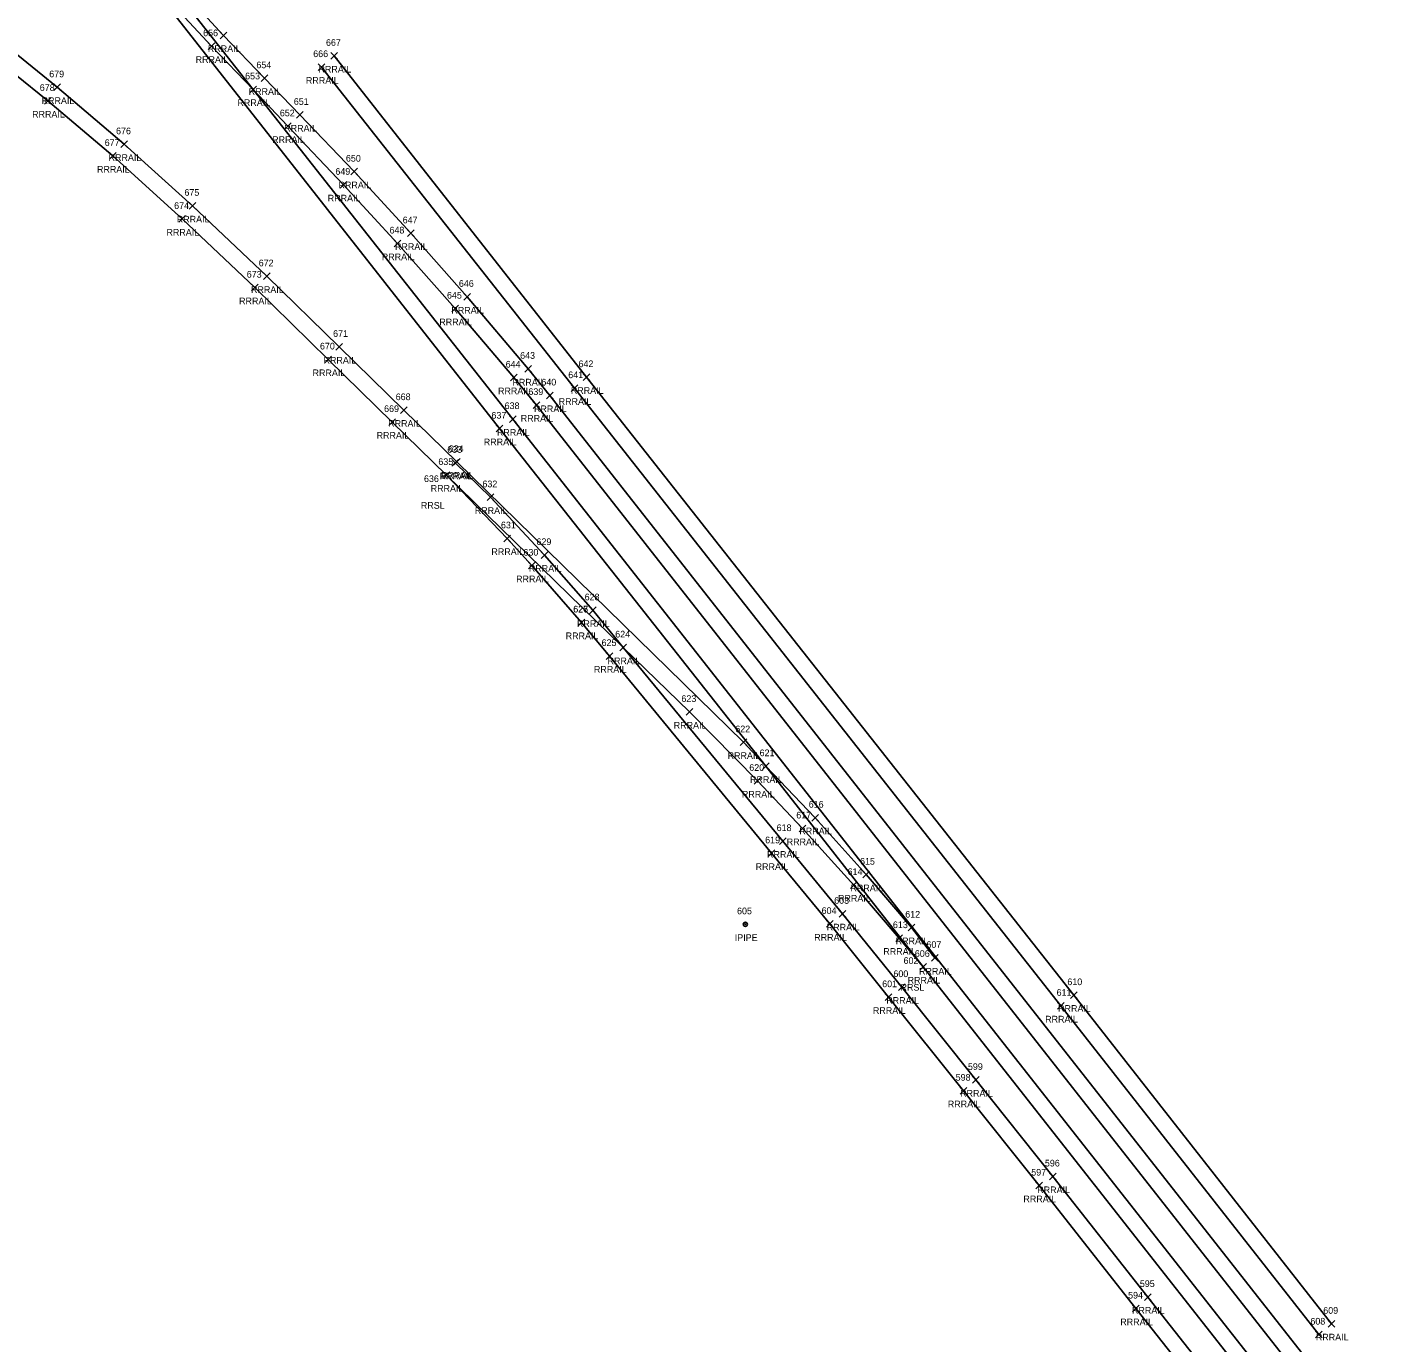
# Model space of a CAD drawing. Extents: x 1615599 to 1619911, y 273782 to 280437.
# Drawn here: x 1616569.8 to 1616981.6, y 279351.3 to 279745.5 of the extents above; entities that cross this region are included whole.
import ezdxf

# ---------------------------------------------------------------- set-up
doc = ezdxf.new("R2010")
doc.units = 0
for name, color, linetype in [('M_A', 7, 'Continuous'), ('M_I', 7, 'Continuous'), ('MPIP', 7, 'Continuous'), ('R_A', 7, 'Continuous'), ('R_I', 7, 'Continuous'), ('R_TIC', 7, 'Continuous'), ('RR', 7, 'Continuous')]:
    doc.layers.add(name, color=color, linetype=linetype)

msp = doc.modelspace()

# ---------------------------------------------------------------- linework, layer by layer
at = {"layer": 'MPIP'}
for radius in [0.625, 0.0833]:
    msp.add_circle((1616785.13, 279476.65), radius, dxfattribs=at)
at = {"layer": 'R_TIC'}
for points in [[(1616627.65, 279742.11), (1616629.65, 279744.11)], [(1616629.65, 279742.11), (1616627.65, 279744.11)], [(1616623.98, 279738.87), (1616625.98, 279740.87)], [(1616625.98, 279738.87), (1616623.98, 279740.87)], [(1616660.82, 279735.98), (1616662.82, 279737.98)], [(1616662.82, 279735.98), (1616660.82, 279737.98)], [(1616657.05, 279732.61), (1616659.05, 279734.61)], [(1616659.05, 279732.61), (1616657.05, 279734.61)], [(1616639.89, 279729.27), (1616641.89, 279731.27)], [(1616641.89, 279729.27), (1616639.89, 279731.27)], [(1616574.93, 279722.48), (1616576.93, 279724.48)], [(1616576.93, 279722.48), (1616574.93, 279724.48)], [(1616577.78, 279726.56), (1616579.78, 279728.56)], [(1616579.78, 279726.56), (1616577.78, 279728.56)], [(1616636.52, 279725.94), (1616638.52, 279727.94)], [(1616638.52, 279725.94), (1616636.52, 279727.94)], [(1616636.52, 279725.94), (1616638.52, 279727.94)], [(1616638.52, 279725.94), (1616636.52, 279727.94)], [(1616646.93, 279714.86), (1616648.93, 279716.86)], [(1616648.93, 279714.86), (1616646.93, 279716.86)], [(1616650.55, 279718.29), (1616652.55, 279720.29)], [(1616652.55, 279718.29), (1616650.55, 279720.29)], [(1616594.4, 279705.97), (1616596.4, 279707.97)], [(1616596.4, 279705.97), (1616594.4, 279707.97)], [(1616597.87, 279709.48), (1616599.87, 279711.48)], [(1616599.87, 279709.48), (1616597.87, 279711.48)], [(1616666.83, 279701.27), (1616668.83, 279703.27)], [(1616668.83, 279701.27), (1616666.83, 279703.27)], [(1616663.6, 279697.33), (1616665.6, 279699.33)], [(1616665.6, 279697.33), (1616663.6, 279699.33)], [(1616618.31, 279691.03), (1616620.31, 279693.03)], [(1616620.31, 279691.03), (1616618.31, 279693.03)], [(1616615.23, 279687.08), (1616617.23, 279689.08)], [(1616617.23, 279687.08), (1616615.23, 279689.08)], [(1616683.77, 279682.78), (1616685.77, 279684.78)], [(1616685.77, 279682.78), (1616683.77, 279684.78)], [(1616679.81, 279679.73), (1616681.81, 279681.73)], [(1616681.81, 279679.73), (1616679.81, 279681.73)], [(1616640.59, 279669.9), (1616642.59, 279671.9)], [(1616642.59, 279669.9), (1616640.59, 279671.9)], [(1616637.01, 279666.5), (1616639.01, 279668.5)], [(1616639.01, 279666.5), (1616637.01, 279668.5)], [(1616700.68, 279663.74), (1616702.68, 279665.74)], [(1616702.68, 279663.74), (1616700.68, 279665.74)], [(1616697.06, 279660.21), (1616699.06, 279662.21)], [(1616699.06, 279660.21), (1616697.06, 279662.21)], [(1616662.34, 279648.74), (1616664.34, 279650.74)], [(1616664.34, 279648.74), (1616662.34, 279650.74)], [(1616659.04, 279644.96), (1616661.04, 279646.96)], [(1616661.04, 279644.96), (1616659.04, 279646.96)], [(1616719, 279642.16), (1616721, 279644.16)], [(1616721, 279642.16), (1616719, 279644.16)], [(1616714.66, 279639.54), (1616716.66, 279641.54)], [(1616716.66, 279639.54), (1616714.66, 279641.54)], [(1616732.86, 279636.36), (1616734.86, 279638.36)], [(1616734.86, 279636.36), (1616732.86, 279638.36)], [(1616736.5, 279639.66), (1616738.5, 279641.66)], [(1616738.5, 279639.66), (1616736.5, 279641.66)], [(1616725.46, 279634.17), (1616727.46, 279636.17)], [(1616727.46, 279634.17), (1616725.46, 279636.17)], [(1616681.72, 279629.77), (1616683.72, 279631.77)], [(1616683.72, 279629.77), (1616681.72, 279631.77)], [(1616721.48, 279631.31), (1616723.48, 279633.31)], [(1616723.48, 279631.31), (1616721.48, 279633.31)], [(1616678.25, 279626.2), (1616680.25, 279628.2)], [(1616680.25, 279626.2), (1616678.25, 279628.2)], [(1616710.4, 279624.23), (1616712.4, 279626.23)], [(1616712.4, 279624.23), (1616710.4, 279626.23)], [(1616714.35, 279627.09), (1616716.35, 279629.09)], [(1616716.35, 279627.09), (1616714.35, 279629.09)], [(1616697.15, 279613.99), (1616699.15, 279615.99)], [(1616699.15, 279613.99), (1616697.15, 279615.99)], [(1616697.57, 279614.23), (1616699.57, 279616.23)], [(1616699.57, 279614.23), (1616697.57, 279616.23)], [(1616694.47, 279610.31), (1616696.47, 279612.31)], [(1616696.47, 279610.31), (1616694.47, 279612.31)], [(1616694.47, 279610.31), (1616696.47, 279612.31)], [(1616696.47, 279610.31), (1616694.47, 279612.31)], [(1616707.69, 279603.66), (1616709.69, 279605.66)], [(1616709.69, 279603.66), (1616707.69, 279605.66)], [(1616712.69, 279591.34), (1616714.69, 279593.34)], [(1616714.69, 279591.34), (1616712.69, 279593.34)], [(1616720.09, 279583.16), (1616722.09, 279585.16)], [(1616722.09, 279583.16), (1616720.09, 279585.16)], [(1616723.91, 279586.33), (1616725.91, 279588.33)], [(1616725.91, 279586.33), (1616723.91, 279588.33)], [(1616734.96, 279566.13), (1616736.96, 279568.13)], [(1616736.96, 279566.13), (1616734.96, 279568.13)], [(1616734.96, 279566.11), (1616736.96, 279568.11)], [(1616736.96, 279566.11), (1616734.96, 279568.11)], [(1616738.35, 279569.76), (1616740.35, 279571.76)], [(1616740.35, 279569.76), (1616738.35, 279571.76)], [(1616747.52, 279558.62), (1616749.52, 279560.62)], [(1616749.52, 279558.62), (1616747.52, 279560.62)], [(1616747.52, 279558.62), (1616749.52, 279560.62)], [(1616749.52, 279558.62), (1616747.52, 279560.62)], [(1616743.42, 279556.06), (1616745.42, 279558.06)], [(1616745.42, 279556.06), (1616743.42, 279558.06)], [(1616767.37, 279539.29), (1616769.37, 279541.29)], [(1616769.37, 279539.29), (1616767.37, 279541.29)], [(1616783.53, 279530.21), (1616785.53, 279532.21)], [(1616785.53, 279530.21), (1616783.53, 279532.21)], [(1616790.25, 279523.04), (1616792.25, 279525.04)], [(1616792.25, 279523.04), (1616790.25, 279525.04)], [(1616790.25, 279523.04), (1616792.25, 279525.04)], [(1616792.25, 279523.04), (1616790.25, 279525.04)], [(1616787.81, 279518.63), (1616789.81, 279520.63)], [(1616789.81, 279518.63), (1616787.81, 279520.63)], [(1616801.25, 279504.36), (1616803.25, 279506.36)], [(1616803.25, 279504.36), (1616801.25, 279506.36)], [(1616805.04, 279507.6), (1616807.04, 279509.6)], [(1616807.04, 279507.6), (1616805.04, 279509.6)], [(1616795.36, 279500.58), (1616797.36, 279502.58)], [(1616797.36, 279500.58), (1616795.36, 279502.58)], [(1616791.93, 279496.92), (1616793.93, 279498.92)], [(1616793.93, 279496.92), (1616791.93, 279498.92)], [(1616820.37, 279490.52), (1616822.37, 279492.52)], [(1616822.37, 279490.52), (1616820.37, 279492.52)], [(1616816.64, 279487.42), (1616818.64, 279489.42)], [(1616818.64, 279487.42), (1616816.64, 279489.42)], [(1616809.5, 279475.75), (1616811.5, 279477.75)], [(1616811.5, 279475.75), (1616809.5, 279477.75)], [(1616809.5, 279475.75), (1616811.5, 279477.75)], [(1616811.5, 279475.75), (1616809.5, 279477.75)], [(1616813.26, 279478.79), (1616815.26, 279480.79)], [(1616815.26, 279478.79), (1616813.26, 279480.79)], [(1616813.26, 279478.79), (1616815.26, 279480.79)], [(1616815.26, 279478.79), (1616813.26, 279480.79)], [(1616830.23, 279471.5), (1616832.23, 279473.5)], [(1616832.23, 279471.5), (1616830.23, 279473.5)], [(1616833.94, 279474.65), (1616835.94, 279476.65)], [(1616835.94, 279474.65), (1616833.94, 279476.65)], [(1616840.94, 279465.55), (1616842.94, 279467.55)], [(1616842.94, 279465.55), (1616840.94, 279467.55)], [(1616837.51, 279462.88), (1616839.51, 279464.88)], [(1616839.51, 279462.88), (1616837.51, 279464.88)], [(1616837.51, 279462.88), (1616839.51, 279464.88)], [(1616839.51, 279462.88), (1616837.51, 279464.88)], [(1616831.11, 279456.81), (1616833.11, 279458.81)], [(1616833.11, 279456.81), (1616831.11, 279458.81)], [(1616827.1, 279453.79), (1616829.1, 279455.79)], [(1616829.1, 279453.79), (1616827.1, 279455.79)], [(1616878.76, 279451.2), (1616880.76, 279453.2)], [(1616880.76, 279451.2), (1616878.76, 279453.2)], [(1616882.64, 279454.4), (1616884.64, 279456.4)], [(1616884.64, 279454.4), (1616882.64, 279456.4)], [(1616853.26, 279428.97), (1616855.26, 279430.97)], [(1616855.26, 279428.97), (1616853.26, 279430.97)], [(1616849.57, 279425.76), (1616851.57, 279427.76)], [(1616851.57, 279425.76), (1616849.57, 279427.76)], [(1616872.24, 279397.31), (1616874.24, 279399.31)], [(1616874.24, 279397.31), (1616872.24, 279399.31)], [(1616876.39, 279400.04), (1616878.39, 279402.04)], [(1616878.39, 279400.04), (1616876.39, 279402.04)], [(1616901.29, 279360.44), (1616903.29, 279362.44)], [(1616903.29, 279360.44), (1616901.29, 279362.44)], [(1616904.81, 279363.9), (1616906.81, 279365.9)], [(1616906.81, 279363.9), (1616904.81, 279365.9)], [(1616956.09, 279352.64), (1616958.09, 279354.64)], [(1616958.09, 279352.64), (1616956.09, 279354.64)], [(1616959.95, 279355.88), (1616961.95, 279357.88)], [(1616961.95, 279355.88), (1616959.95, 279357.88)]]:
    msp.add_lwpolyline(points, dxfattribs=at)
at = {"layer": 'RR'}
for points in [[(1618859.75, 276891.53), (1618799.24, 276968.15), (1618284.94, 277623.12), (1618268.81, 277643.64), (1617626.81, 278460.24), (1617616.13, 278473.64), (1617546.95, 278561.72), (1617499.49, 278621.79), (1617406.55, 278740.52), (1617357.63, 278802.9), (1617271.97, 278912.55), (1616838.51, 279463.88), (1616791.25, 279524.04), (1616711.4, 279625.23), (1616195.43, 280281.84), (1616147.06, 280342.91)], [(1618863.67, 276894.43), (1618803.13, 276971.25), (1618287.89, 277627.49), (1618272.16, 277647.46), (1617630.42, 278463.6), (1617620.37, 278476.22), (1617582.75, 278523.92), (1617266.97, 278926.89), (1616715.35, 279628.09), (1616637.52, 279726.94), (1616590.36, 279786.85), (1616151.06, 280346.19)], [(1617630.42, 278463.6), (1617620.82, 278476.43), (1617606.54, 278496.62), (1617593.5, 278516.12), (1617586.3, 278527.38), (1617567.87, 278556.66), (1617553.59, 278578.19), (1617540.33, 278596.98), (1617518.68, 278626.03), (1617484.75, 278670.09), (1617274.79, 278937.46), (1616726.46, 279635.17), (1616720, 279643.16), (1616701.68, 279664.74), (1616684.77, 279683.78), (1616667.83, 279702.27), (1616651.55, 279719.29), (1616640.89, 279730.27), (1616628.65, 279743.11), (1616617.88, 279754.77), (1616607.15, 279767.18), (1616599.77, 279774.94), (1616590.36, 279786.85)], [(1617627.18, 278460.59), (1617616.67, 278473.78), (1617602.72, 278493.41), (1617589.08, 278513.87), (1617582.75, 278523.92), (1617563.26, 278554.55), (1617549.48, 278575.26), (1617536.29, 278594.04), (1617514.68, 278623.03), (1617480.83, 278667.07), (1617271.03, 278934.24), (1616722.48, 279632.31), (1616715.66, 279640.54), (1616698.06, 279661.21), (1616680.81, 279680.73), (1616664.6, 279698.33), (1616647.93, 279715.86), (1616637.52, 279726.94), (1616624.98, 279739.87), (1616614.3, 279751.39), (1616603.44, 279763.78), (1616596.48, 279772.09), (1616586.32, 279784.93)], [(1616841.94, 279466.55), (1616834.94, 279475.65), (1616821.37, 279491.52), (1616806.04, 279508.6), (1616791.25, 279524.04), (1616784.53, 279531.21), (1616698.57, 279615.23), (1616682.72, 279630.77), (1616663.34, 279649.74), (1616641.59, 279670.9), (1616619.31, 279692.03), (1616598.87, 279710.48), (1616578.78, 279727.56), (1616559.36, 279743.25)], [(1616838.51, 279463.88), (1616831.23, 279472.5), (1616817.64, 279488.42), (1616802.25, 279505.36), (1616788.81, 279519.63), (1616768.37, 279540.29), (1616748.52, 279559.62), (1616695.47, 279611.31), (1616679.25, 279627.2), (1616660.04, 279645.96), (1616638.01, 279667.5), (1616616.23, 279688.08), (1616595.4, 279706.97), (1616575.93, 279723.48), (1616556.08, 279739.45)], [(1616960.95, 279356.88), (1616883.64, 279455.4), (1616737.5, 279640.66), (1616661.82, 279736.98)], [(1616957.09, 279353.64), (1616879.76, 279452.2), (1616733.86, 279637.36), (1616658.05, 279733.61)], [(1616814.26, 279479.79), (1616796.36, 279501.58), (1616748.52, 279559.62), (1616739.35, 279570.76), (1616724.91, 279587.33), (1616708.69, 279604.66), (1616698.15, 279614.99)], [(1616810.5, 279476.75), (1616792.93, 279497.92), (1616744.42, 279557.06), (1616735.96, 279567.13), (1616735.96, 279567.11), (1616721.09, 279584.16), (1616713.69, 279592.34), (1616695.47, 279611.31)], [(1617410, 278743.26), (1617396.66, 278759.99), (1617376.07, 278783.25), (1617357.63, 278802.9), (1617338.99, 278821.92), (1617323.11, 278838.2), (1617305.76, 278857.56), (1617286.13, 278880.85), (1617265.43, 278906.99), (1617008.7, 279234.06), (1616973.07, 279279.43), (1616937.09, 279325.15), (1616905.81, 279364.9), (1616877.39, 279401.04), (1616854.26, 279429.97), (1616832.11, 279457.81), (1616814.26, 279479.79)], [(1617406.55, 278740.52), (1617392.93, 278756.85), (1617371.79, 278780.66), (1617353.75, 278799.89), (1617335.51, 278818.43), (1617319.77, 278834.69), (1617301.78, 278854.53), (1617282.18, 278877.78), (1617261.42, 278904), (1617004.64, 279231.09), (1616969.14, 279276.29), (1616932.72, 279322.9), (1616902.29, 279361.44), (1616873.24, 279398.31), (1616850.57, 279426.76), (1616828.1, 279454.79), (1616810.5, 279476.75)]]:
    msp.add_lwpolyline(points, dxfattribs=at)

# ---------------------------------------------------------------- texts
at = {"layer": 'M_A'}
msp.add_text('IPIPE', height=2, dxfattribs=at).set_placement((1616781.96, 279471.65))
at = {"layer": 'M_I'}
msp.add_text('605', height=2, dxfattribs=at).set_placement((1616782.64, 279479.65))
at = {"layer": 'R_A'}
for s, p in [('RRRAIL', (1616620.27, 279734.87)), ('RRRAIL', (1616623.94, 279738.11)), ('RRRAIL', (1616657.11, 279731.98)), ('RRRAIL', (1616653.34, 279728.61)), ('RRRAIL', (1616574.07, 279722.56)), ('RRRAIL', (1616636.18, 279725.27)), ('RRRAIL', (1616571.22, 279718.48)), ('RRRAIL', (1616632.81, 279721.94)), ('RRRAIL', (1616632.81, 279721.94)), ('RRRAIL', (1616646.84, 279714.29)), ('RRRAIL', (1616643.22, 279710.86)), ('RRRAIL', (1616590.69, 279701.97)), ('RRRAIL', (1616594.16, 279705.48)), ('RRRAIL', (1616663.12, 279697.27)), ('RRRAIL', (1616659.89, 279693.33)), ('RRRAIL', (1616614.61, 279687.03)), ('RRRAIL', (1616611.52, 279683.08)), ('RRRAIL', (1616680.06, 279678.78)), ('RRRAIL', (1616676.1, 279675.73)), ('RRRAIL', (1616636.88, 279665.9)), ('RRRAIL', (1616633.3, 279662.5)), ('RRRAIL', (1616696.97, 279659.74)), ('RRRAIL', (1616693.35, 279656.21)), ('RRRAIL', (1616658.63, 279644.74)), ('RRRAIL', (1616655.34, 279640.96)), ('RRRAIL', (1616715.29, 279638.16)), ('RRRAIL', (1616710.95, 279635.54)), ('RRRAIL', (1616729.15, 279632.36)), ('RRRAIL', (1616732.79, 279635.66)), ('RRRAIL', (1616721.75, 279630.17)), ('RRRAIL', (1616678.02, 279625.77)), ('RRRAIL', (1616717.77, 279627.31)), ('RRRAIL', (1616674.55, 279622.2)), ('RRRAIL', (1616706.69, 279620.23)), ('RRRAIL', (1616710.64, 279623.09)), ('RRRAIL', (1616693.44, 279609.99)), ('RRRAIL', (1616693.86, 279610.23)), ('RRRAIL', (1616690.76, 279606.31)), ('RRRAIL', (1616690.76, 279606.31)), ('RRSL', (1616687.82, 279601.21)), ('RRRAIL', (1616703.99, 279599.66)), ('RRRAIL', (1616708.98, 279587.34)), ('RRRAIL', (1616716.38, 279579.16)), ('RRRAIL', (1616720.2, 279582.33)), ('RRRAIL', (1616731.25, 279562.13)), ('RRRAIL', (1616731.25, 279562.11)), ('RRRAIL', (1616734.64, 279565.76)), ('RRRAIL', (1616743.81, 279554.62)), ('RRRAIL', (1616743.81, 279554.62)), ('RRRAIL', (1616739.72, 279552.06)), ('RRRAIL', (1616763.66, 279535.29)), ('RRRAIL', (1616779.82, 279526.21)), ('RRRAIL', (1616786.54, 279519.04)), ('RRRAIL', (1616786.54, 279519.04)), ('RRRAIL', (1616784.1, 279514.63)), ('RRRAIL', (1616797.54, 279500.36)), ('RRRAIL', (1616801.33, 279503.6)), ('RRRAIL', (1616791.65, 279496.58)), ('RRRAIL', (1616788.22, 279492.92)), ('RRRAIL', (1616816.66, 279486.52)), ('RRRAIL', (1616812.93, 279483.42)), ('RRRAIL', (1616805.79, 279471.75)), ('RRRAIL', (1616805.79, 279471.75)), ('RRRAIL', (1616809.55, 279474.79)), ('RRRAIL', (1616809.55, 279474.79)), ('RRRAIL', (1616826.52, 279467.5)), ('RRRAIL', (1616830.23, 279470.65)), ('RRRAIL', (1616833.8, 279458.88)), ('RRRAIL', (1616833.8, 279458.88)), ('RRRAIL', (1616837.23, 279461.55)), ('RRSL', (1616831.67, 279456.76)), ('RRRAIL', (1616827.4, 279452.81)), ('RRRAIL', (1616823.39, 279449.79)), ('RRRAIL', (1616875.05, 279447.2)), ('RRRAIL', (1616878.93, 279450.4)), ('RRRAIL', (1616849.55, 279424.97)), ('RRRAIL', (1616845.86, 279421.76)), ('RRRAIL', (1616868.53, 279393.31)), ('RRRAIL', (1616872.68, 279396.04)), ('RRRAIL', (1616897.58, 279356.44)), ('RRRAIL', (1616901.1, 279359.9)), ('RRRAIL', (1616956.24, 279351.88))]:
    msp.add_text(s, height=2, dxfattribs=at).set_placement(p)
at = {"layer": 'R_I'}
for s, p in [('656', (1616622.52, 279742.87)), ('667', (1616659.36, 279739.98)), ('666', (1616655.54, 279736.61)), ('654', (1616638.48, 279733.27)), ('679', (1616576.36, 279730.56)), ('653', (1616635.11, 279729.94)), ('653', (1616635.11, 279729.94)), ('678', (1616573.52, 279726.48)), ('652', (1616645.52, 279718.86)), ('651', (1616649.71, 279722.29)), ('676', (1616596.4, 279713.48)), ('677', (1616592.99, 279709.97)), ('650', (1616665.34, 279705.27)), ('649', (1616662.18, 279701.33)), ('675', (1616616.9, 279695.03)), ('674', (1616613.82, 279691.08)), ('647', (1616682.36, 279686.78)), ('648', (1616678.4, 279683.73)), ('672', (1616639.18, 279673.9)), ('673', (1616635.6, 279670.5)), ('646', (1616699.22, 279667.74)), ('645', (1616695.65, 279664.21)), ('671', (1616661.49, 279652.74)), ('670', (1616657.55, 279648.96)), ('643', (1616717.59, 279646.16)), ('644', (1616713.25, 279643.54)), ('641', (1616732.02, 279640.36)), ('642', (1616735.09, 279643.66)), ('640', (1616723.96, 279638.17)), ('668', (1616680.27, 279633.77)), ('639', (1616720.06, 279635.31)), ('669', (1616676.79, 279630.2)), ('637', (1616708.99, 279628.23)), ('638', (1616712.94, 279631.09)), ('633', (1616695.74, 279617.99)), ('634', (1616696.16, 279618.23)), ('635', (1616693.06, 279614.31)), ('635', (1616693.06, 279614.31)), ('636', (1616688.75, 279609.21)), ('632', (1616706.28, 279607.66)), ('631', (1616711.84, 279595.34)), ('630', (1616718.59, 279587.16)), ('629', (1616722.49, 279590.33)), ('626', (1616733.5, 279570.13)), ('627', (1616733.55, 279570.11)), ('628', (1616736.94, 279573.76)), ('624', (1616746.11, 279562.62)), ('624', (1616746.11, 279562.62)), ('625', (1616742.02, 279560.06)), ('623', (1616765.96, 279543.29)), ('622', (1616782.12, 279534.21)), ('621', (1616789.41, 279527.04)), ('621', (1616789.41, 279527.04)), ('620', (1616786.31, 279522.63)), ('617', (1616800.41, 279508.36)), ('616', (1616804.15, 279511.6)), ('618', (1616794.52, 279504.58)), ('619', (1616791.08, 279500.92)), ('615', (1616819.53, 279494.52)), ('614', (1616815.8, 279491.42)), ('604', (1616808.01, 279479.75)), ('604', (1616808.01, 279479.75)), ('603', (1616811.77, 279482.79)), ('603', (1616811.77, 279482.79)), ('613', (1616829.39, 279475.5)), ('612', (1616833.09, 279478.65)), ('607', (1616839.45, 279469.55)), ('602', (1616832.58, 279464.76)), ('606', (1616835.97, 279466.88)), ('606', (1616835.97, 279466.88)), ('600', (1616829.54, 279460.81)), ('601', (1616826.18, 279457.79)), ('611', (1616878.49, 279455.2)), ('610', (1616881.71, 279458.4)), ('599', (1616851.89, 279432.97)), ('598', (1616848.21, 279429.76)), ('597', (1616870.88, 279401.31)), ('596', (1616874.97, 279404.04)), ('594', (1616899.93, 279364.44)), ('595', (1616903.45, 279367.9)), ('608', (1616954.6, 279356.64)), ('609', (1616958.46, 279359.88))]:
    msp.add_text(s, height=2, dxfattribs=at).set_placement(p)

doc.saveas('drawing.dxf')
